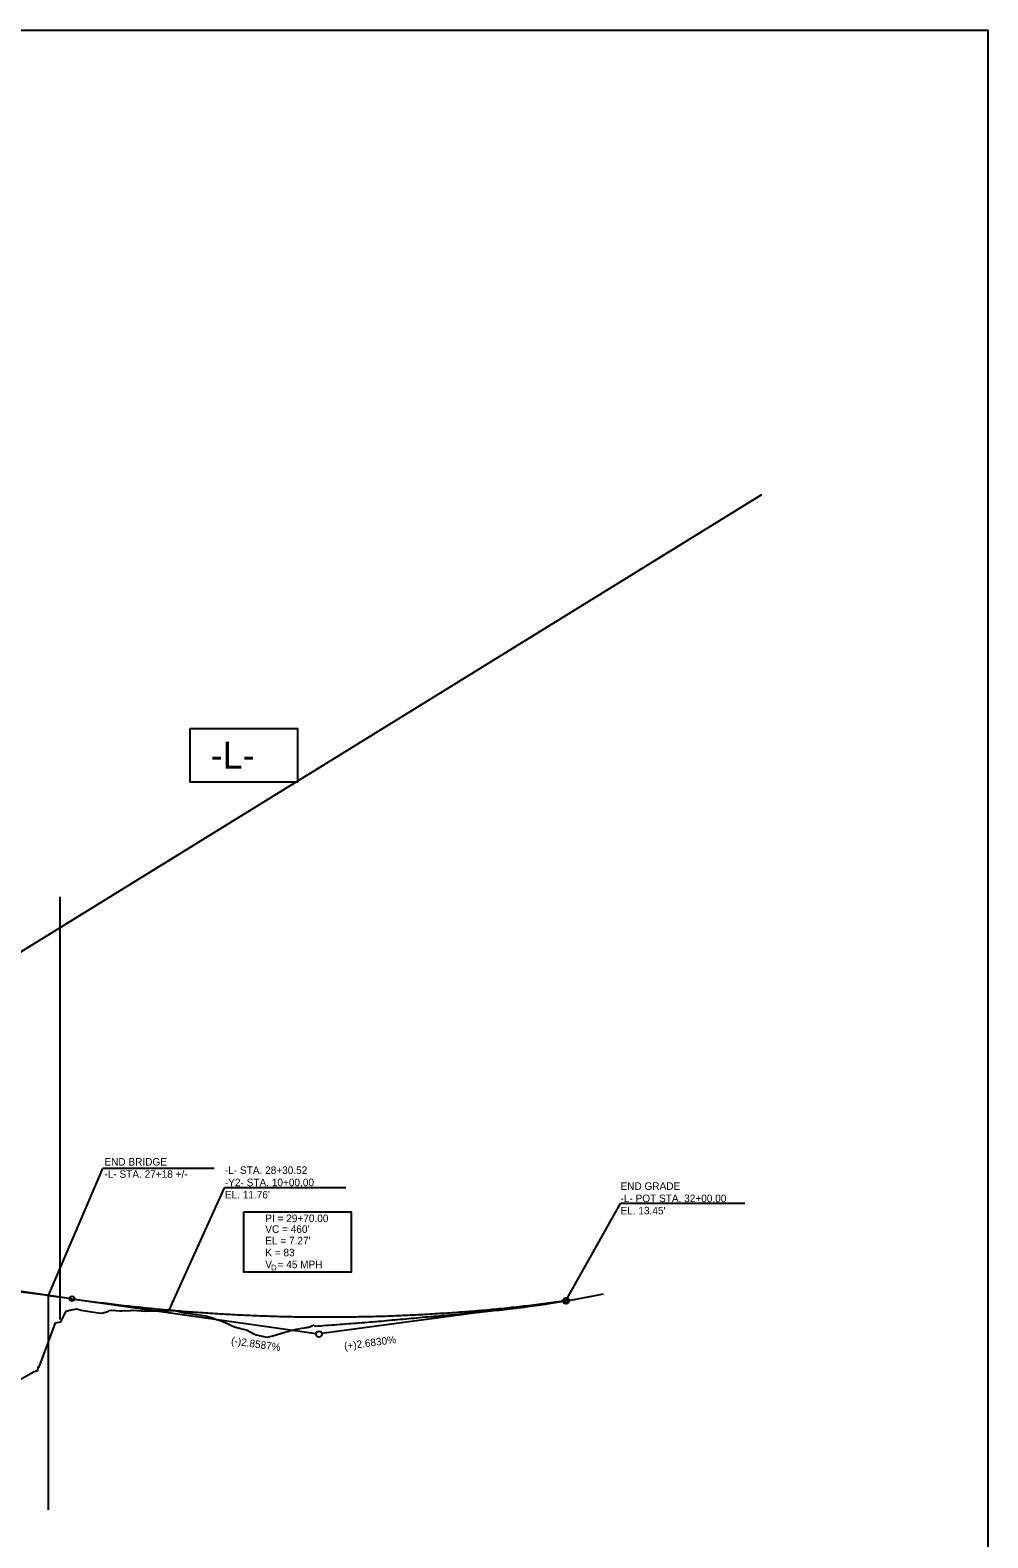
# Model space of a CAD drawing. Extents: x 1626634 to 1638383, y 876896 to 886347.
# Drawn here: x 1629503 to 1630395, y 882354 to 883757 of the extents above; entities that cross this region are included whole.
import ezdxf

# ---------------------------------------------------------------- set-up
doc = ezdxf.new("R2010")
doc.units = 0
for name, color, linetype in [('Exist Vertical Profile Ground Line', 7, 'Continuous'), ('Prop Roadway Bridge', 7, 'Continuous'), ('Prop Vertical Profile Curve Label', 7, 'Continuous'), ('Prop Vertical Profile Grade', 7, 'Continuous'), ('Prop Vertical Profile Grade Label', 7, 'Continuous'), ('Prop VPI Label', 7, 'Continuous')]:
    doc.layers.add(name, color=color, linetype=linetype)

msp = doc.modelspace()

# ---------------------------------------------------------------- linework, layer by layer
at = {"layer": 'Exist Vertical Profile Ground Line'}
msp.add_lwpolyline([(1629485.7, 882497.2), (1629506.5, 882508.9), (1629509.8, 882509.7), (1629510.2, 882513.2), (1629510.6, 882512.5), (1629513.1, 882518.7), (1629526.1, 882554.1), (1629531.3, 882555.1), (1629536.1, 882565.1), (1629540.7, 882566.3), (1629546.1, 882567.3), (1629550.2, 882566), (1629556.1, 882564.9), (1629559.7, 882564.4), (1629566.2, 882563.4), (1629569.7, 882563.2), (1629575.5, 882564.9), (1629576.2, 882565.6), (1629578.6, 882565.9), (1629586.2, 882565.2), (1629588.1, 882565.2), (1629596.2, 882565.7), (1629597.6, 882565.8), (1629606.2, 882565.2), (1629607.1, 882565.2), (1629608.8, 882565.1), (1629617.8, 882565.3), (1629623.6, 882565.2), (1629636, 882565.6), (1629637.1, 882565.5), (1629646.4, 882563.6), (1629647.2, 882563.6), (1629663.9, 882561.1), (1629666.3, 882560.6), (1629673.4, 882558.5), (1629676.3, 882557.2), (1629679.6, 882556.4), (1629686.4, 882553.6), (1629690.2, 882551.7), (1629692.9, 882550.3), (1629701, 882548.4), (1629702.5, 882547.9), (1629704.1, 882547.7), (1629711.6, 882543.6), (1629713, 882542.9), (1629723, 882540.9), (1629728.5, 882542.2), (1629732.8, 882543.3), (1629739.8, 882545.4), (1629742.6, 882546), (1629744.4, 882546.8), (1629749.5, 882548.1), (1629750.4, 882548.2), (1629751.3, 882548.4), (1629752.9, 882548.7), (1629755.5, 882549.1), (1629758, 882549.5), (1629759.8, 882549.8), (1629760.6, 882549.9), (1629761, 882550), (1629761.5, 882550.1), (1629762.1, 882550.1), (1629763.1, 882550.5), (1629765.7, 882551.6), (1629766.6, 882551.9), (1629768.2, 882551.4), (1629768.8, 882551.2), (1629770.8, 882551.3), (1629771.2, 882551.3), (1629772, 882551.4), (1629773.4, 882551.5), (1629775.9, 882551.7), (1629778.5, 882551.9), (1629781, 882552), (1629783.9, 882552.2), (1629786.1, 882552.4), (1629788.7, 882552.6), (1629791.2, 882552.8), (1629791.9, 882552.9), (1629793.8, 882553), (1629796.3, 882553.2), (1629798.9, 882553.4), (1629800, 882553.5), (1629801.4, 882553.6), (1629804, 882553.8), (1629806.5, 882554), (1629808.2, 882554.1), (1629809.1, 882554.2), (1629811.7, 882554.4), (1629814.2, 882554.6), (1629816.8, 882554.8), (1629819.3, 882555), (1629820.8, 882555.1), (1629821.9, 882555.2), (1629824.4, 882555.4), (1629825.5, 882555.5), (1629827, 882555.6), (1629829.5, 882555.8), (1629832.1, 882556.1), (1629834.6, 882556.3), (1629837.2, 882556.5), (1629839.7, 882556.8), (1629840.5, 882556.8), (1629841.9, 882556.9), (1629842.3, 882557), (1629844.8, 882557.2), (1629847.4, 882557.5), (1629850, 882557.7), (1629852.5, 882557.9), (1629855.1, 882558.2), (1629857.6, 882558.4), (1629859.7, 882558.6), (1629860.2, 882558.6), (1629862.7, 882558.9), (1629865.3, 882559.1), (1629867.8, 882559.3), (1629870.4, 882559.6), (1629871.2, 882559.6), (1629872.9, 882559.8), (1629875.5, 882560), (1629878, 882560.2), (1629879.2, 882560.3), (1629879.8, 882560.3), (1629880.6, 882560.4), (1629883.1, 882560.6), (1629885.7, 882560.9), (1629888.3, 882561.1), (1629890.8, 882561.3), (1629893.4, 882561.5), (1629895.9, 882561.7), (1629898.5, 882562), (1629899.2, 882562), (1629901, 882562.2), (1629903.6, 882562.5), (1629906.1, 882562.7), (1629908.7, 882563), (1629911.2, 882563.3), (1629913.8, 882563.5), (1629916.3, 882563.8), (1629918.9, 882564), (1629920.7, 882564.2), (1629921, 882564.2), (1629921.5, 882564.3), (1629924, 882564.5), (1629926.6, 882564.8), (1629929.1, 882565.1), (1629931.7, 882565.3), (1629934.2, 882565.6), (1629936.8, 882565.9), (1629939.3, 882566.1), (1629941.9, 882566.4), (1629942.8, 882566.5), (1629943.1, 882566.5), (1629944.4, 882566.7), (1629947, 882567), (1629949.5, 882567.3), (1629952.1, 882567.6), (1629954.6, 882567.9), (1629957.2, 882568.2), (1629959.8, 882568.5), (1629962.8, 882568.8), (1629963.5, 882568.9), (1629982.8, 882571.6), (1629983.8, 882571.8), (1630005, 882575.1), (1630005.7, 882575.3), (1630027.3, 882579.4), (1630036.7, 882581.3)], dxfattribs=at)
at = {"layer": 'Prop Roadway Bridge'}
msp.add_line((1629519.8, 882380), (1629519.8, 882579.7), dxfattribs=at)
at = {"layer": 'Prop Vertical Profile Curve Label'}
for p, q in [((1630183.7, 883324.8), (1627555.3, 881704.1)), ((1629530.6, 882557.4), (1629530.6, 882950.5))]:
    msp.add_line(p, q, dxfattribs=at)
msp.add_lwpolyline([(1626634.5, 883757.1), (1630394.5, 883757.1), (1630394.5, 881162.5), (1626634.5, 881162.5)], close=True, dxfattribs=at)
for centre in [(1629541.6, 882576.6), (1629541.6, 882576.6), (1630001.6, 882574.6)]:
    msp.add_circle(centre, 2.25, dxfattribs=at)
at = {"layer": 'Prop Vertical Profile Grade'}
for points in [[(1628551.6, 882584.1), (1628571.4, 882586.5), (1628591.2, 882588.9), (1628611, 882591.2), (1628630.8, 882593.3), (1628650.6, 882595.4), (1628670.4, 882597.3), (1628690.2, 882599.2), (1628710, 882600.9), (1628729.8, 882602.5), (1628749.6, 882604), (1628769.4, 882605.4), (1628789.2, 882606.7), (1628809, 882607.9), (1628828.8, 882609), (1628848.6, 882610), (1628868.4, 882610.8), (1628888.2, 882611.6), (1628908, 882612.3), (1628927.8, 882612.8), (1628947.6, 882613.3), (1628967.4, 882613.6), (1628987.2, 882613.8), (1629007, 882613.9), (1629026.8, 882613.9), (1629046.6, 882613.8), (1629066.4, 882613.6), (1629086.2, 882613.3), (1629106, 882612.9), (1629125.8, 882612.4), (1629145.6, 882611.8), (1629165.4, 882611), (1629185.2, 882610.2), (1629205, 882609.2), (1629224.8, 882608.2), (1629244.6, 882607), (1629264.4, 882605.7), (1629284.2, 882604.3), (1629304, 882602.8), (1629323.8, 882601.3), (1629343.6, 882599.5), (1629363.4, 882597.7), (1629383.2, 882595.8), (1629403, 882593.8), (1629422.8, 882591.7), (1629442.6, 882589.4), (1629462.4, 882587.1), (1629482.2, 882584.6), (1629502, 882582.1), (1629521.8, 882579.4), (1629541.6, 882576.6)], [(1629541.6, 882576.6), (1629550.8, 882575.3), (1629560, 882574.1), (1629569.2, 882572.9), (1629578.4, 882571.8), (1629587.6, 882570.7), (1629596.8, 882569.6), (1629606, 882568.7), (1629615.2, 882567.7), (1629624.4, 882566.8), (1629633.6, 882566), (1629642.8, 882565.2), (1629652, 882564.5), (1629661.2, 882563.8), (1629670.4, 882563.2), (1629679.6, 882562.6), (1629688.8, 882562.1), (1629698, 882561.6), (1629707.2, 882561.2), (1629716.4, 882560.8), (1629725.6, 882560.5), (1629734.8, 882560.2), (1629744, 882560), (1629753.2, 882559.8), (1629762.4, 882559.7), (1629771.6, 882559.7), (1629780.8, 882559.7), (1629790, 882559.7), (1629799.2, 882559.8), (1629808.4, 882559.9), (1629817.6, 882560.1), (1629826.8, 882560.3), (1629836, 882560.6), (1629845.2, 882561), (1629854.4, 882561.4), (1629863.6, 882561.8), (1629872.8, 882562.3), (1629882, 882562.9), (1629891.2, 882563.4), (1629900.4, 882564.1), (1629909.6, 882564.8), (1629918.8, 882565.5), (1629928, 882566.3), (1629937.2, 882567.2), (1629946.4, 882568.1), (1629955.6, 882569.1), (1629964.8, 882570.1), (1629974, 882571.1), (1629983.2, 882572.2), (1629992.4, 882573.4), (1630001.6, 882574.6)]]:
    msp.add_spline(points, degree=3, dxfattribs=at)
at = {"layer": 'Prop VPI Label'}
for p, q in [((1629519.8, 882579.7), (1629570.4, 882697.9)), ((1629674.1, 882697.9), (1629570.4, 882697.9)), ((1629632, 882566.1), (1629683.6, 882679.7)), ((1629796.7, 882679.7), (1629683.6, 882679.7)), ((1630001.6, 882574.6), (1630052.4, 882665.3)), ((1630168.3, 882665.3), (1630052.4, 882665.3)), ((1629541.6, 882576.6), (1629049.4, 882647)), ((1629541.6, 882576.6), (1629768.9, 882544.1)), ((1630001.6, 882574.6), (1629774.4, 882544.1))]:
    msp.add_line(p, q, dxfattribs=at)
for points in [[(1629651.6, 883107.4), (1629751.6, 883107.4), (1629751.6, 883057.4), (1629651.6, 883057.4)], [(1629651.6, 883107.4), (1629751.6, 883107.4), (1629751.6, 883057.4), (1629651.6, 883057.4)], [(1629651.6, 883107.4), (1629751.6, 883107.4), (1629751.6, 883057.4), (1629651.6, 883057.4)], [(1629651.6, 883107.4), (1629751.6, 883107.4), (1629751.6, 883057.4), (1629651.6, 883057.4)], [(1629701.6, 882657.4), (1629801.6, 882657.4), (1629801.6, 882601.2), (1629701.6, 882601.2)], [(1629701.6, 882657.4), (1629801.6, 882657.4), (1629801.6, 882601.2), (1629701.6, 882601.2)]]:
    msp.add_lwpolyline(points, close=True, dxfattribs=at)
for centre in [(1630001.6, 882574.6), (1629771.6, 882543.7)]:
    msp.add_circle(centre, 2.75, dxfattribs=at)

# ---------------------------------------------------------------- texts
at = {"layer": 'Prop Vertical Profile Curve Label'}
for s, height, p in [('-L-', 25, (1629670.8, 883069.9)), ("VC = 460'", 7, (1629721.6, 882637.9)), ('K = 83', 7, (1629721.6, 882616.1))]:
    msp.add_text(s, height=height, dxfattribs=at).set_placement(p)
for s, height, p in [('V  = 45 MPH', 7, (1629721.6, 882605)), ('D', 5.25, (1629727.1, 882603))]:
    msp.add_text(s, height=height, rotation=360, dxfattribs=at).set_placement(p)
at = {"layer": 'Prop Vertical Profile Grade Label'}
for s, rotation, p in [('(-)2.8587%', 351.8654, (1629689.5, 882534.3)), ('(+)2.6830%', 7.6406, (1629795.5, 882528.9))]:
    msp.add_text(s, height=7, rotation=rotation, dxfattribs=at).set_placement(p)
at = {"layer": 'Prop VPI Label'}
for s, p in [('END BRIDGE', (1629571.8, 882700.5)), ('-L- STA. 27+18 +/-', (1629571.8, 882689.1)), ('-L- STA. 28+30.52', (1629684, 882692.7)), ('-Y2- STA. 10+00.00', (1629684, 882681.3)), ("EL. 11.76'", (1629684, 882669.9)), ('-L- POT STA. 32+00.00', (1630052.4, 882666.5)), ('END GRADE', (1630052.4, 882677.9)), ("EL. 13.45'", (1630052.4, 882655.1)), ('PI = 29+70.00', (1629721.6, 882647.9)), ("EL = 7.27'", (1629721.6, 882627.2))]:
    msp.add_text(s, height=7, dxfattribs=at).set_placement(p)

doc.saveas('drawing.dxf')
